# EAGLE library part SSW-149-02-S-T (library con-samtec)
THROUGH-HOLE .025" SQ POST SOCKET Source: Samtec SSW.pdf
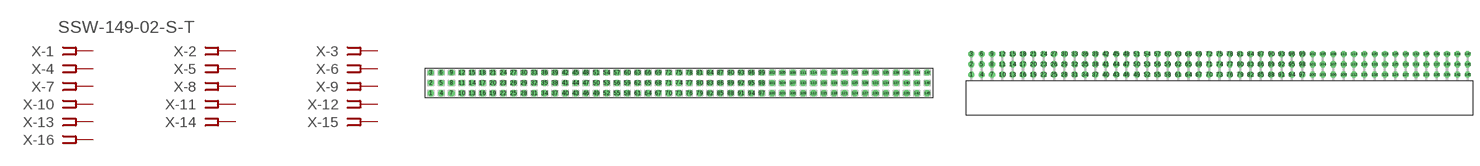
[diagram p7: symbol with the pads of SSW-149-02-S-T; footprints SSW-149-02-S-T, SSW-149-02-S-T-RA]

Designator prefix X; gates -1=FPINV -2=FPIN -3=FPIN -4=FPIN -5=FPIN -6=FPIN -7=FPIN -8=FPIN -9=FPIN -10=FPIN -11=FPIN -12=FPIN -13=FPIN -14=FPIN -15=FPIN -16=FPIN -17=FPIN -18=FPIN -19=FPIN -20=FPIN -21=FPIN -22=FPIN -23=FPIN -24=FPIN -25=FPIN -26=FPIN -27=FPIN -28=FPIN -29=FPIN -30=FPIN -31=FPIN -32=FPIN -33=FPIN -34=FPIN -35=FPIN -36=FPIN -37=FPIN -38=FPIN -39=FPIN -40=FPIN -41=FPIN -42=FPIN -43=FPIN -44=FPIN -45=FPIN -46=FPIN -47=FPIN -48=FPIN -49=FPIN -50=FPIN -51=FPIN -52=FPIN -53=FPIN -54=FPIN -55=FPIN -56=FPIN -57=FPIN -58=FPIN -59=FPIN -60=FPIN -61=FPIN -62=FPIN -63=FPIN -64=FPIN -65=FPIN -66=FPIN -67=FPIN -68=FPIN -69=FPIN -70=FPIN -71=FPIN -72=FPIN -73=FPIN -74=FPIN -75=FPIN -76=FPIN -77=FPIN -78=FPIN -79=FPIN -80=FPIN -81=FPIN -82=FPIN -83=FPIN -84=FPIN -85=FPIN -86=FPIN -87=FPIN -88=FPIN -89=FPIN -90=FPIN -91=FPIN -92=FPIN -93=FPIN -94=FPIN -95=FPIN -96=FPIN -97=FPIN -98=FPIN -99=FPIN -100=FPIN -101=FPIN -102=FPIN -103=FPIN -104=FPIN -105=FPIN -106=FPIN -107=FPIN -108=FPIN -109=FPIN -110=FPIN -111=FPIN -112=FPIN -113=FPIN -114=FPIN -115=FPIN -116=FPIN -117=FPIN -118=FPIN -119=FPIN -120=FPIN -121=FPIN -122=FPIN -123=FPIN -124=FPIN -125=FPIN -126=FPIN -127=FPIN -128=FPIN -129=FPIN -130=FPIN -131=FPIN -132=FPIN -133=FPIN -134=FPIN -135=FPIN -136=FPIN -137=FPIN -138=FPIN -139=FPIN -140=FPIN -141=FPIN -142=FPIN -143=FPIN -144=FPIN -145=FPIN -146=FPIN -147=FPIN

## SSW-149-02-S-T (OC_FARNELL: unknown; OC_NEWARK: unknown)  [SSW-149-02-S-T]
1  -1:1  pas
2  -2:1  pas
3  -3:1  pas
4  -4:1  pas
5  -5:1  pas
6  -6:1  pas
7  -7:1  pas
8  -8:1  pas
9  -9:1  pas
10  -10:1  pas
11  -11:1  pas
12  -12:1  pas
13  -13:1  pas
14  -14:1  pas
15  -15:1  pas
16  -16:1  pas
17  -17:1  pas
18  -18:1  pas
19  -19:1  pas
20  -20:1  pas
21  -21:1  pas
22  -22:1  pas
23  -23:1  pas
24  -24:1  pas
25  -25:1  pas
26  -26:1  pas
27  -27:1  pas
28  -28:1  pas
29  -29:1  pas
30  -30:1  pas
31  -31:1  pas
32  -32:1  pas
33  -33:1  pas
34  -34:1  pas
35  -35:1  pas
36  -36:1  pas
37  -37:1  pas
38  -38:1  pas
39  -39:1  pas
40  -40:1  pas
41  -41:1  pas
42  -42:1  pas
43  -43:1  pas
44  -44:1  pas
45  -45:1  pas
46  -46:1  pas
47  -47:1  pas
48  -48:1  pas
49  -49:1  pas
50  -50:1  pas
51  -51:1  pas
52  -52:1  pas
53  -53:1  pas
54  -54:1  pas
55  -55:1  pas
56  -56:1  pas
57  -57:1  pas
58  -58:1  pas
59  -59:1  pas
60  -60:1  pas
61  -61:1  pas
62  -62:1  pas
63  -63:1  pas
64  -64:1  pas
65  -65:1  pas
66  -66:1  pas
67  -67:1  pas
68  -68:1  pas
69  -69:1  pas
70  -70:1  pas
71  -71:1  pas
72  -72:1  pas
73  -73:1  pas
74  -74:1  pas
75  -75:1  pas
76  -76:1  pas
77  -77:1  pas
78  -78:1  pas
79  -79:1  pas
80  -80:1  pas
81  -81:1  pas
82  -82:1  pas
83  -83:1  pas
84  -84:1  pas
85  -85:1  pas
86  -86:1  pas
87  -87:1  pas
88  -88:1  pas
89  -89:1  pas
90  -90:1  pas
91  -91:1  pas
92  -92:1  pas
93  -93:1  pas
94  -94:1  pas
95  -95:1  pas
96  -96:1  pas
97  -97:1  pas
98  -98:1  pas
99  -99:1  pas
100  -100:1  pas
101  -101:1  pas
102  -102:1  pas
103  -103:1  pas
104  -104:1  pas
105  -105:1  pas
106  -106:1  pas
107  -107:1  pas
108  -108:1  pas
109  -109:1  pas
110  -110:1  pas
111  -111:1  pas
112  -112:1  pas
113  -113:1  pas
114  -114:1  pas
115  -115:1  pas
116  -116:1  pas
117  -117:1  pas
118  -118:1  pas
119  -119:1  pas
120  -120:1  pas
121  -121:1  pas
122  -122:1  pas
123  -123:1  pas
124  -124:1  pas
125  -125:1  pas
126  -126:1  pas
127  -127:1  pas
128  -128:1  pas
129  -129:1  pas
130  -130:1  pas
131  -131:1  pas
132  -132:1  pas
133  -133:1  pas
134  -134:1  pas
135  -135:1  pas
136  -136:1  pas
137  -137:1  pas
138  -138:1  pas
139  -139:1  pas
140  -140:1  pas
141  -141:1  pas
142  -142:1  pas
143  -143:1  pas
144  -144:1  pas
145  -145:1  pas
146  -146:1  pas
147  -147:1  pas

## SSW-149-02-S-TRA (OC_FARNELL: unknown; OC_NEWARK: unknown)  [SSW-149-02-S-T-RA]
Pads as for SSW-149-02-S-T

## Footprint SSW-149-02-S-T (pad centres in mm)
THROUGH-HOLE .025" SQ POST SOCKET Source: Samtec SSW.pdf
drill 1 pad 1.5 octagon: 1 -60.96,-2.54; 2 -60.96,0; 3 -60.96,2.54; 4 -58.42,-2.54; 5 -58.42,0; 6 -58.42,2.54; 7 -55.88,-2.54; 8 -55.88,0; 9 -55.88,2.54; 10 -53.34,-2.54; 11 -53.34,0; 12 -53.34,2.54; 13 -50.8,-2.54; 14 -50.8,0; 15 -50.8,2.54; 16 -48.26,-2.54; 17 -48.26,0; 18 -48.26,2.54; 19 -45.72,-2.54; 20 -45.72,0; 21 -45.72,2.54; 22 -43.18,-2.54; 23 -43.18,0; 24 -43.18,2.54; 25 -40.64,-2.54; 26 -40.64,0; 27 -40.64,2.54; 28 -38.1,-2.54; 29 -38.1,0; 30 -38.1,2.54; 31 -35.56,-2.54; 32 -35.56,0; 33 -35.56,2.54; 34 -33.02,-2.54; 35 -33.02,0; 36 -33.02,2.54; 37 -30.48,-2.54; 38 -30.48,0; 39 -30.48,2.54; 40 -27.94,-2.54; 41 -27.94,0; 42 -27.94,2.54; 43 -25.4,-2.54; 44 -25.4,0; 45 -25.4,2.54; 46 -22.86,-2.54; 47 -22.86,0; 48 -22.86,2.54; 49 -20.32,-2.54; 50 -20.32,0; 51 -20.32,2.54; 52 -17.78,-2.54; 53 -17.78,0; 54 -17.78,2.54; 55 -15.24,-2.54; 56 -15.24,0; 57 -15.24,2.54; 58 -12.7,-2.54; 59 -12.7,0; 60 -12.7,2.54; 61 -10.16,-2.54; 62 -10.16,0; 63 -10.16,2.54; 64 -7.62,-2.54; 65 -7.62,0; 66 -7.62,2.54; 67 -5.08,-2.54; 68 -5.08,0; 69 -5.08,2.54; 70 -2.54,-2.54; 71 -2.54,0; 72 -2.54,2.54; 73 0,-2.54; 74 0,0; 75 0,2.54; 76 2.54,-2.54; 77 2.54,0; 78 2.54,2.54; 79 5.08,-2.54; 80 5.08,0; 81 5.08,2.54; 82 7.62,-2.54; 83 7.62,0; 84 7.62,2.54; 85 10.16,-2.54; 86 10.16,0; 87 10.16,2.54; 88 12.7,-2.54; 89 12.7,0; 90 12.7,2.54; 91 15.24,-2.54; 92 15.24,0; 93 15.24,2.54; 94 17.78,-2.54; 95 17.78,0; 96 17.78,2.54; 97 20.32,-2.54; 98 20.32,0; 99 20.32,2.54; 100 22.86,-2.54; 101 22.86,0; 102 22.86,2.54; 103 25.4,-2.54; 104 25.4,0; 105 25.4,2.54; 106 27.94,-2.54; 107 27.94,0; 108 27.94,2.54; 109 30.48,-2.54; 110 30.48,0; 111 30.48,2.54; 112 33.02,-2.54; 113 33.02,0; 114 33.02,2.54; 115 35.56,-2.54; 116 35.56,0; 117 35.56,2.54; 118 38.1,-2.54; 119 38.1,0; 120 38.1,2.54; 121 40.64,-2.54; 122 40.64,0; 123 40.64,2.54; 124 43.18,-2.54; 125 43.18,0; 126 43.18,2.54; 127 45.72,-2.54; 128 45.72,0; 129 45.72,2.54; 130 48.26,-2.54; 131 48.26,0; 132 48.26,2.54; 133 50.8,-2.54; 134 50.8,0; 135 50.8,2.54; 136 53.34,-2.54; 137 53.34,0; 138 53.34,2.54; 139 55.88,-2.54; 140 55.88,0; 141 55.88,2.54; 142 58.42,-2.54; 143 58.42,0; 144 58.42,2.54; 145 60.96,-2.54; 146 60.96,0; 147 60.96,2.54

## Footprint SSW-149-02-S-T-RA (pad centres in mm)
THROUGH-HOLE .025" SQ POST SOCKET Source: Samtec SSW.pdf
drill 1 pad 1.5 octagon: 1 -60.96,1.524; 2 -60.96,4.064; 3 -60.96,6.604; 4 -58.42,1.524; 5 -58.42,4.064; 6 -58.42,6.604; 7 -55.88,1.524; 8 -55.88,4.064; 9 -55.88,6.604; 10 -53.34,1.524; 11 -53.34,4.064; 12 -53.34,6.604; 13 -50.8,1.524; 14 -50.8,4.064; 15 -50.8,6.604; 16 -48.26,1.524; 17 -48.26,4.064; 18 -48.26,6.604; 19 -45.72,1.524; 20 -45.72,4.064; 21 -45.72,6.604; 22 -43.18,1.524; 23 -43.18,4.064; 24 -43.18,6.604; 25 -40.64,1.524; 26 -40.64,4.064; 27 -40.64,6.604; 28 -38.1,1.524; 29 -38.1,4.064; 30 -38.1,6.604; 31 -35.56,1.524; 32 -35.56,4.064; 33 -35.56,6.604; 34 -33.02,1.524; 35 -33.02,4.064; 36 -33.02,6.604; 37 -30.48,1.524; 38 -30.48,4.064; 39 -30.48,6.604; 40 -27.94,1.524; 41 -27.94,4.064; 42 -27.94,6.604; 43 -25.4,1.524; 44 -25.4,4.064; 45 -25.4,6.604; 46 -22.86,1.524; 47 -22.86,4.064; 48 -22.86,6.604; 49 -20.32,1.524; 50 -20.32,4.064; 51 -20.32,6.604; 52 -17.78,1.524; 53 -17.78,4.064; 54 -17.78,6.604; 55 -15.24,1.524; 56 -15.24,4.064; 57 -15.24,6.604; 58 -12.7,1.524; 59 -12.7,4.064; 60 -12.7,6.604; 61 -10.16,1.524; 62 -10.16,4.064; 63 -10.16,6.604; 64 -7.62,1.524; 65 -7.62,4.064; 66 -7.62,6.604; 67 -5.08,1.524; 68 -5.08,4.064; 69 -5.08,6.604; 70 -2.54,1.524; 71 -2.54,4.064; 72 -2.54,6.604; 73 0,1.524; 74 0,4.064; 75 0,6.604; 76 2.54,1.524; 77 2.54,4.064; 78 2.54,6.604; 79 5.08,1.524; 80 5.08,4.064; 81 5.08,6.604; 82 7.62,1.524; 83 7.62,4.064; 84 7.62,6.604; 85 10.16,1.524; 86 10.16,4.064; 87 10.16,6.604; 88 12.7,1.524; 89 12.7,4.064; 90 12.7,6.604; 91 15.24,1.524; 92 15.24,4.064; 93 15.24,6.604; 94 17.78,1.524; 95 17.78,4.064; 96 17.78,6.604; 97 20.32,1.524; 98 20.32,4.064; 99 20.32,6.604; 100 22.86,1.524; 101 22.86,4.064; 102 22.86,6.604; 103 25.4,1.524; 104 25.4,4.064; 105 25.4,6.604; 106 27.94,1.524; 107 27.94,4.064; 108 27.94,6.604; 109 30.48,1.524; 110 30.48,4.064; 111 30.48,6.604; 112 33.02,1.524; 113 33.02,4.064; 114 33.02,6.604; 115 35.56,1.524; 116 35.56,4.064; 117 35.56,6.604; 118 38.1,1.524; 119 38.1,4.064; 120 38.1,6.604; 121 40.64,1.524; 122 40.64,4.064; 123 40.64,6.604; 124 43.18,1.524; 125 43.18,4.064; 126 43.18,6.604; 127 45.72,1.524; 128 45.72,4.064; 129 45.72,6.604; 130 48.26,1.524; 131 48.26,4.064; 132 48.26,6.604; 133 50.8,1.524; 134 50.8,4.064; 135 50.8,6.604; 136 53.34,1.524; 137 53.34,4.064; 138 53.34,6.604; 139 55.88,1.524; 140 55.88,4.064; 141 55.88,6.604; 142 58.42,1.524; 143 58.42,4.064; 144 58.42,6.604; 145 60.96,1.524; 146 60.96,4.064; 147 60.96,6.604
